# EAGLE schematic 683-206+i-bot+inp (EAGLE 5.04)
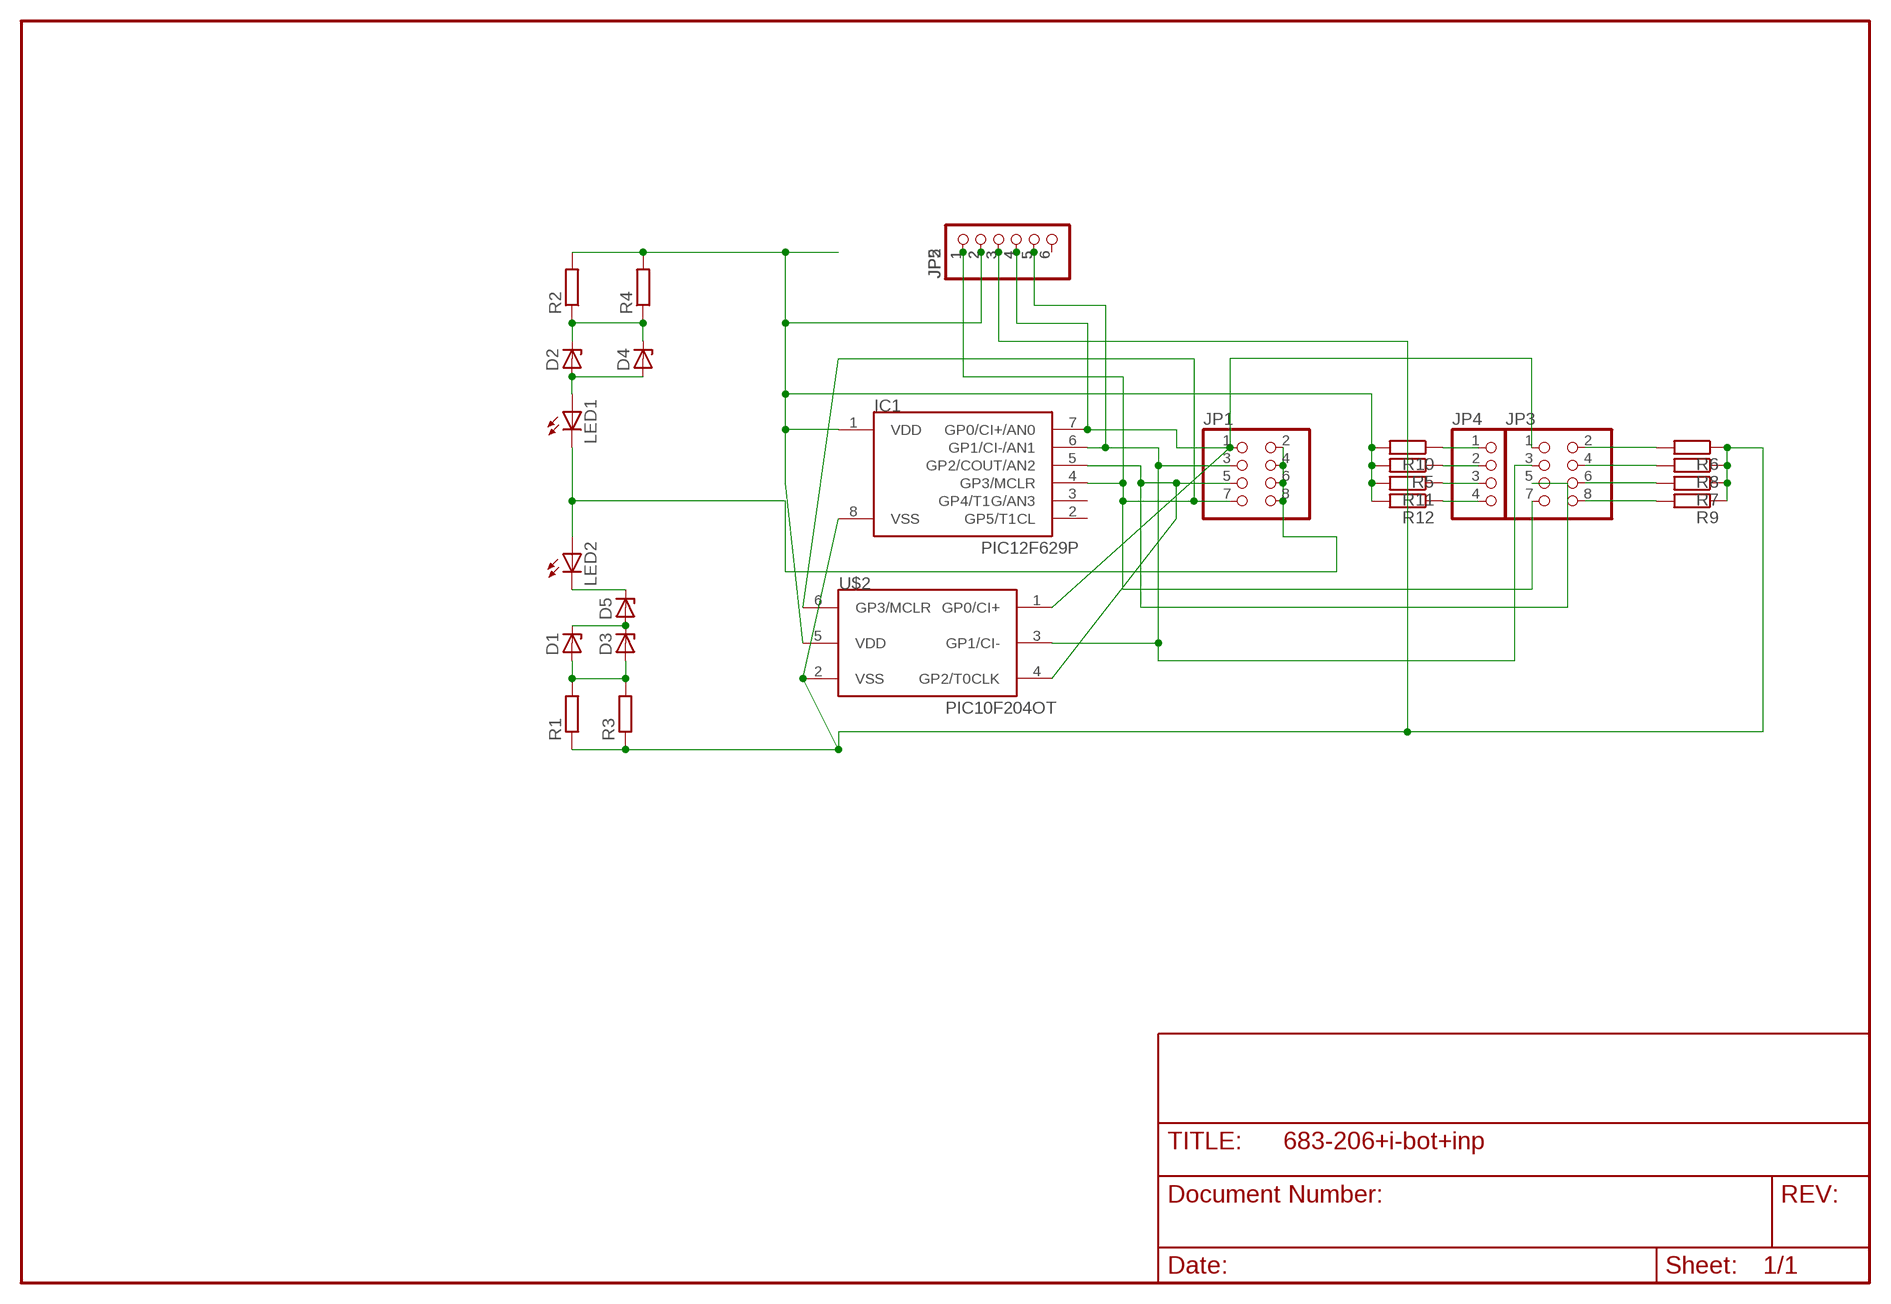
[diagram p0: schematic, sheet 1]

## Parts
D1  ZENER-DIODESOT23  [SOT23]
D2  ZENER-DIODESOT23  [SOT23]
D3  ZENER-DIODEZD-2.5  [ZDIO-2.5]
D4  ZENER-DIODEZD-2.5  [ZDIO-2.5]
D5  ZENER-DIODESOD80C  [SOD80C]
IC1  PIC12F629P  [DIL8]
JP1  PINHD-2X4  [2X04]
JP2  PINHD-1X6  [1X06]
JP3  PINHD-2X4  [2X04]
JP4  PINHD-1X4  [1X04]
JP5  PINHD-1X6  [1X06]
LED1  LED5MM  [LED5MM]
LED2  LED5MM  [LED5MM]
R1  R-EU_0204/2V  [0204V]
R2  R-EU_0204/2V  [0204V]
R3  R-EU_R1206  [R1206]
R4  R-EU_R1206  [R1206]
R5  R-EU_R1206  [R1206]
R6  R-EU_R1206  [R1206]
R7  R-EU_R1206  [R1206]
R8  R-EU_R1206  [R1206]
R9  R-EU_R1206  [R1206]
R10  R-EU_R1206  [R1206]
R11  R-EU_R1206  [R1206]
R12  R-EU_R1206  [R1206]
U$2  PIC10F204OT  [SOT23-6]

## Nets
N$1: IC1.6(GP1/CI-/AN1) JP1.3 JP2.5 JP3.3 JP5.5 U$2.3(GP1/CI-)
N$2: D1.3(C) D3.C D5.A
N$3: D1.1(A) D3.A R1.2 R3.2
N$4: JP1.2 JP1.4 JP1.6 JP1.8 LED1.K(C) LED2.A
N$5: IC1.8(VSS) JP2.3 JP5.3 R1.1 R3.1 R6.1 R7.1 R8.1 R9.1 U$2.2(VSS)
N$6: IC1.1(VDD) JP2.2 JP5.2 R2.2 R4.2 R5.2 R10.2 R11.2 R12.2 U$2.5(VDD)
N$7: D2.1(A) D4.A LED1.A
N$8: D2.3(C) D4.C R2.1 R4.1
N$9: IC1.5(GP2/COUT/AN2) JP1.5 JP3.5 U$2.4(GP2/T0CLK)
N$10: IC1.4(GP3/MCLR) JP1.7 JP2.1 JP3.7 JP5.1 U$2.6(GP3/MCLR)
N$11: D5.C LED2.K(C)
N$13: JP2.6 JP5.6
N$14: IC1.7(GP0/CI+/AN0) JP1.1 JP2.4 JP3.1 JP5.4 U$2.1(GP0/CI+)
N$15: JP4.4 R12.1
N$16: JP4.3 R11.1
N$17: JP4.2 R5.1
N$18: JP4.1 R10.1
N$19: JP3.8 R9.2
N$20: JP3.6 R7.2
N$21: JP3.4 R8.2
N$22: JP3.2 R6.2
Unconnected: IC1.2(GP5/T1CL) IC1.3(GP4/T1G/AN3)

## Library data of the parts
D1-D5 = diode-1:ZENER-DIODE: Z-Diode
IC1 = microchip-5:PIC12F6*: uPC nW 1k Program Flash memory 2x Timer Comparator 10b A/D converter/ 4xIN
JP1 JP3 = pinhead:PINHD-2X4: PIN HEADER
JP2 JP5 = pinhead:PINHD-1X6: PIN HEADER
JP4 = pinhead(2):PINHD-1X4: PIN HEADER
LED1 LED2 = led:LED: LED
R1-R12 = rcl-2:R-EU_: RESISTOR, European symbol
U$2 = microchip-5:PIC10F2*: uPC nW 0,25/0,5k Program Flash memory Comparator

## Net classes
0 default: width 0.3 mm, drill 0.6 mm, clearance 0.2 mm
1 power: width 0.4 mm, drill 0.6 mm, clearance 0.2 mm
